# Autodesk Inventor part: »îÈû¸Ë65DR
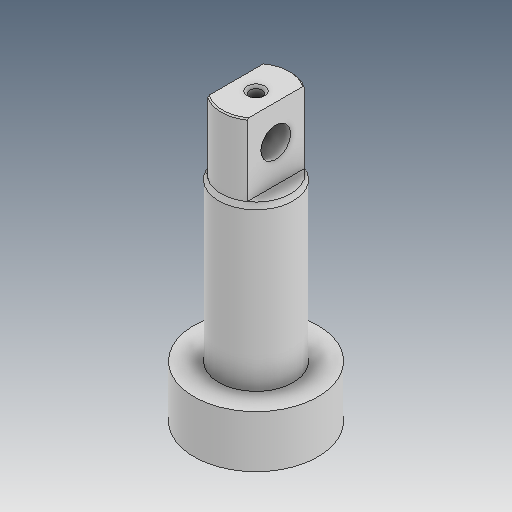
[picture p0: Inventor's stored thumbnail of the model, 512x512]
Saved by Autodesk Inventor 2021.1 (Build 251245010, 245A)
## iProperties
Created: 2019-04
Part Number: »îÈû¸Ë65DR
Material: Ogólny
Document SubType Name: Modeling
Designer: user
Density: 1 g/cm^3
Appearance: Domyślna
Author: user
Revision Number: ÈÎºÎ
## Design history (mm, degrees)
feature "µ¹½Ç2"
node "Bryła1"
